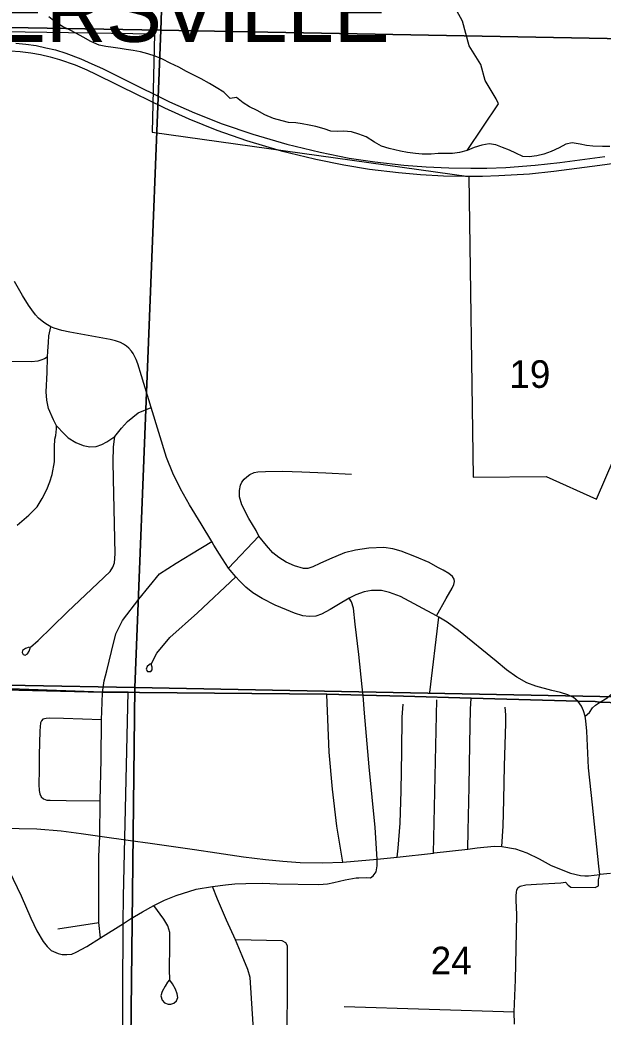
# Model space of a CAD drawing. Extents: x -19 to 40.8, y -1.8 to 26.1.
# Drawn here: x 6.121 to 7.005, y 15.443 to 16.956 of the extents above; entities that cross this region are included whole.
import ezdxf

# ---------------------------------------------------------------- set-up
doc = ezdxf.new("R2010")
doc.units = 0
for name, color, linetype in [('GM_X_City_Street', 7, 'Continuous'), ('GM_X_Corporation', 7, 'Continuous'), ('GM_X_Major_River_Text', 7, 'Continuous'), ('GM_X_Rail_Line', 7, 'Continuous'), ('GM_X_Rail_Line_Text', 7, 'Continuous'), ('GM_X_Section', 7, 'Continuous'), ('GM_X_Section_Text', 7, 'Continuous'), ('GM_X_State_Route', 7, 'Continuous'), ('GM_X_Township_Road', 7, 'Continuous'), ('RW_P_Text', 7, 'Continuous')]:
    doc.layers.add(name, color=color, linetype=linetype)

msp = doc.modelspace()

# ---------------------------------------------------------------- linework, layer by layer
at = {"layer": 'GM_X_City_Street'}
for points in [[(5.6389, 16.9451), (6.325, 16.9348), (6.3216, 16.7856), (6.8016, 16.7183), (6.8081, 16.2623), (6.9186, 16.2633), (6.995, 16.2287), (7.0882, 16.4448)], [(6.2755, 15.1522), (6.2776, 15.5857), (6.2778, 15.6259), (6.2851, 15.9362), (6.2469, 15.9361), (6.0635, 15.9423)]]:
    msp.add_lwpolyline(points, dxfattribs=at)
at = {"layer": 'GM_X_Corporation'}
for points in [[(6.0683, 15.7291), (6.093, 15.7296), (6.1466, 15.7285), (6.1833, 15.7258), (6.2138, 15.7217), (6.2422, 15.7176)], [(6.0683, 15.7291), (6.0733, 15.7128), (6.0759, 15.7091), (6.0816, 15.7026), (6.0877, 15.6959), (6.0929, 15.689), (6.1229, 15.6269), (6.1373, 15.5931), (6.1466, 15.5737), (6.1562, 15.5575), (6.1621, 15.5501), (6.1685, 15.5443), (6.1791, 15.5394), (6.1851, 15.5381), (6.1921, 15.5378), (6.1997, 15.5386), (6.2062, 15.5414), (6.2224, 15.5504), (6.2431, 15.5632), (6.2778, 15.5852), (6.2888, 15.5919)], [(6.2422, 15.7176), (6.2886, 15.711), (6.3184, 15.7069)], [(6.3184, 15.7069), (6.3857, 15.6974), (6.4194, 15.6924), (6.4601, 15.6863), (6.493, 15.6823), (6.5195, 15.6795), (6.546, 15.6778), (6.5796, 15.6773), (6.6104, 15.6781), (6.6623, 15.6827), (6.6928, 15.6858), (6.7481, 15.6919), (6.749, 15.692)], [(6.749, 15.692), (6.7999, 15.6978), (6.814, 15.6999), (6.8397, 15.7023), (6.8517, 15.7019), (6.8722, 15.6982), (6.8892, 15.6921), (6.9082, 15.6832), (6.9265, 15.6732), (6.9556, 15.6612), (6.9708, 15.6581), (6.9771, 15.6573), (6.983, 15.6572), (6.9998, 15.6594)], [(6.6349, 15.6544), (6.646, 15.6546), (6.6524, 15.6544), (6.6564, 15.6573), (6.6612, 15.6633), (6.6626, 15.6723), (6.6623, 15.6827)], [(6.2888, 15.5919), (6.3066, 15.6028), (6.3238, 15.6124), (6.34, 15.6204), (6.3577, 15.6276), (6.3882, 15.6371), (6.413, 15.6413), (6.4324, 15.6439), (6.4468, 15.6452), (6.4632, 15.6459), (6.4885, 15.6461), (6.511, 15.6452), (6.5739, 15.644), (6.5871, 15.6451), (6.597, 15.647), (6.6142, 15.6512), (6.6309, 15.6544), (6.6349, 15.6544)]]:
    msp.add_lwpolyline(points, dxfattribs=at)
at = {"layer": 'GM_X_Rail_Line'}
for points in [[(6.9998, 15.6594), (6.9986, 15.672), (6.9888, 15.7651), (6.983, 15.8213), (6.9801, 15.8766), (6.9786, 15.8925), (6.9776, 15.8996), (6.9753, 15.9076), (6.9725, 15.9147), (6.9674, 15.9218), (6.9601, 15.9277), (6.9513, 15.9321), (6.9403, 15.9355), (6.9272, 15.9385), (6.9031, 15.9449), (6.8894, 15.9502), (6.8744, 15.9586), (6.8587, 15.9699), (6.8429, 15.9828), (6.7859, 16.0296), (6.7684, 16.0421), (6.7559, 16.0497), (6.7523, 16.052), (6.6977, 16.0809), (6.6813, 16.0874), (6.6691, 16.0902), (6.6541, 16.0902), (6.6427, 16.0882), (6.6304, 16.0837), (6.6203, 16.0785), (6.6038, 16.0688), (6.5911, 16.0612), (6.578, 16.0544), (6.5696, 16.0514), (6.5596, 16.0506), (6.5499, 16.0519), (6.537, 16.0558), (6.5249, 16.0607), (6.5079, 16.0678), (6.488, 16.0779), (6.4741, 16.0869), (6.4634, 16.0954), (6.4536, 16.1047), (6.4482, 16.1107), (6.4397, 16.1209), (6.437, 16.1242), (6.4233, 16.1454), (6.4151, 16.1592), (6.4119, 16.1643), (6.3955, 16.1912), (6.378, 16.2201), (6.3642, 16.2444), (6.3526, 16.2683), (6.3431, 16.292), (6.3198, 16.3679), (6.3055, 16.4157), (6.2997, 16.434), (6.2973, 16.4406), (6.2949, 16.4459), (6.2927, 16.4498), (6.2901, 16.4534), (6.2861, 16.4577), (6.2824, 16.4608), (6.2781, 16.4638), (6.2733, 16.4662), (6.2659, 16.4689), (6.2579, 16.4708), (6.2354, 16.475), (6.1964, 16.4822), (6.1847, 16.4848), (6.1731, 16.4884), (6.1679, 16.4904), (6.1628, 16.4932), (6.1589, 16.4956), (6.1549, 16.4986), (6.1492, 16.5035), (6.1446, 16.5084), (6.1388, 16.516), (6.1341, 16.5231), (6.1251, 16.5378), (6.113, 16.559)], [(7.0162, 15.661), (6.9998, 15.6594)]]:
    msp.add_lwpolyline(points, dxfattribs=at)
at = {"layer": 'GM_X_Rail_Line_Text'}
for p, q in [((6.437, 16.1242), (6.4831, 16.1724)), ((6.7425, 15.9355), (6.7559, 16.0497)), ((6.7481, 15.6919), (6.7529, 15.9246)), ((6.6124, 15.4591), (6.8704, 15.4511))]:
    msp.add_line(p, q, dxfattribs=at)
for points in [[(6.1168, 16.1895), (6.1345, 16.2043), (6.1472, 16.2172), (6.1545, 16.2296), (6.162, 16.2436), (6.1664, 16.2553), (6.1697, 16.2662), (6.1736, 16.2856), (6.1732, 16.3081), (6.1737, 16.3198), (6.1752, 16.3254), (6.1763, 16.3353), (6.1765, 16.3402), (6.1718, 16.3492), (6.1645, 16.3662), (6.1618, 16.3791), (6.161, 16.3918), (6.1622, 16.4209), (6.163, 16.4441), (6.1634, 16.4534), (6.1642, 16.4662), (6.165, 16.4763), (6.1679, 16.4904)], [(6.1622, 16.444), (6.1581, 16.4416), (6.1525, 16.4395), (6.1479, 16.4382), (6.1385, 16.437), (6.1089, 16.4378)], [(6.1349, 16.004), (6.1292, 16.002), (6.1248, 15.9994), (6.1242, 15.996), (6.126, 15.9933), (6.1287, 15.9921), (6.1326, 15.9942), (6.1348, 15.9981), (6.1369, 16.004), (6.1487, 16.0143), (6.1691, 16.0347), (6.1931, 16.0577), (6.2203, 16.0837), (6.2577, 16.1192), (6.2618, 16.1255), (6.2643, 16.1322), (6.2655, 16.1459), (6.2627, 16.2596), (6.2623, 16.2853), (6.263, 16.3081), (6.2646, 16.3236), (6.2749, 16.3367), (6.2841, 16.3464), (6.3, 16.3595), (6.3198, 16.3679)], [(6.1765, 16.3402), (6.188, 16.3279), (6.1943, 16.322), (6.2056, 16.3147), (6.2168, 16.31), (6.2271, 16.3082), (6.2368, 16.3089), (6.2452, 16.3116), (6.2529, 16.3157), (6.2646, 16.3236)], [(6.7523, 16.052), (6.7672, 16.0782), (6.776, 16.0936), (6.7787, 16.0992), (6.7799, 16.1037), (6.7791, 16.1075), (6.7765, 16.1116), (6.7714, 16.1162), (6.7628, 16.1211), (6.7544, 16.1253), (6.7411, 16.1325), (6.7196, 16.1416), (6.699, 16.1497), (6.6864, 16.1533), (6.6724, 16.1556), (6.6499, 16.1544), (6.6296, 16.1516), (6.6128, 16.1473), (6.5904, 16.1378), (6.5754, 16.1312), (6.565, 16.1262), (6.5572, 16.1237), (6.551, 16.1236), (6.5372, 16.1274), (6.5248, 16.1334), (6.5137, 16.1403), (6.5046, 16.1475), (6.4949, 16.1584), (6.4831, 16.1724), (6.479, 16.1812), (6.4679, 16.1994), (6.4572, 16.2201), (6.4539, 16.2324), (6.4537, 16.2417), (6.4554, 16.2501), (6.4575, 16.2548), (6.4608, 16.2591), (6.465, 16.2628), (6.4696, 16.266), (6.4759, 16.2691), (6.4816, 16.2703), (6.4932, 16.2707), (6.5191, 16.2712), (6.5485, 16.2702), (6.5846, 16.2686), (6.6235, 16.2667)], [(6.246, 15.9355), (6.2488, 15.953), (6.2526, 15.9684), (6.2598, 15.9977), (6.2665, 16.0244), (6.2765, 16.0447), (6.3014, 16.0771), (6.3327, 16.1156), (6.358, 16.1319), (6.381, 16.1459), (6.4119, 16.1643)], [(6.3188, 15.9791), (6.3168, 15.9776), (6.3137, 15.9749), (6.3126, 15.971), (6.3145, 15.9672), (6.3194, 15.9672), (6.3215, 15.9701), (6.3216, 15.9739), (6.3204, 15.9767), (6.3202, 15.9797), (6.3286, 15.9951), (6.348, 16.0187), (6.39, 16.0563), (6.4482, 16.1107)], [(6.6623, 15.6827), (6.6594, 15.7309), (6.6504, 15.8227), (6.6435, 15.904), (6.6411, 15.9308), (6.6399, 15.9442), (6.6345, 15.9929), (6.6294, 16.0391), (6.6265, 16.0636), (6.6235, 16.0732), (6.6203, 16.0785)], [(6.6104, 15.6781), (6.6012, 15.7326), (6.5947, 15.789), (6.5898, 15.8451), (6.5863, 15.9324)], [(6.6928, 15.6858), (6.6944, 15.6993), (6.6972, 15.737), (6.6987, 15.7865), (6.6998, 15.8461), (6.7006, 15.8979), (6.7021, 15.9179)], [(6.7999, 15.6978), (6.8006, 15.7255), (6.8018, 15.7923), (6.8031, 15.8574), (6.8038, 15.9106), (6.8052, 15.9263), (6.8053, 15.9276)], [(6.8517, 15.7019), (6.8537, 15.7328), (6.8544, 15.7726), (6.8557, 15.8244), (6.8573, 15.8884), (6.8577, 15.9017), (6.8567, 15.9132)], [(6.8707, 15.4323), (6.8704, 15.4511), (6.8724, 15.4996), (6.873, 15.5471), (6.8741, 15.5985), (6.8733, 15.6198), (6.8734, 15.6276), (6.8736, 15.6321), (6.8743, 15.6362), (6.8761, 15.6396), (6.8795, 15.6419), (6.8877, 15.6436), (6.9038, 15.6448), (6.9409, 15.6467), (6.9482, 15.6477), (6.9519, 15.6431), (6.9563, 15.64), (6.993, 15.6399), (6.9982, 15.6421), (6.9979, 15.6513), (6.9998, 15.6594)], [(6.4757, 15.4162), (6.4734, 15.4482), (6.4699, 15.5033), (6.4667, 15.5155), (6.4577, 15.5361), (6.4476, 15.5604), (6.4343, 15.5899), (6.4204, 15.6218), (6.413, 15.6413)], [(6.3477, 15.4994), (6.3448, 15.4958), (6.3414, 15.4899), (6.3366, 15.482), (6.3348, 15.4755), (6.3365, 15.4688), (6.3402, 15.4647), (6.3457, 15.4626), (6.3499, 15.4628), (6.3545, 15.4641), (6.3583, 15.4676), (6.3604, 15.473), (6.3595, 15.4785), (6.3569, 15.4854), (6.3523, 15.4935), (6.3483, 15.4992), (6.3479, 15.5159), (6.3484, 15.551), (6.3482, 15.5712), (6.3454, 15.5815), (6.339, 15.5916), (6.3238, 15.6124)], [(6.4753, 15.3941), (6.4893, 15.3939), (6.5009, 15.3972), (6.5112, 15.4054), (6.5216, 15.4188), (6.5249, 15.424), (6.5262, 15.4322), (6.5264, 15.4768), (6.5267, 15.5513), (6.5241, 15.5559), (6.5184, 15.5586), (6.4476, 15.5604)]]:
    msp.add_lwpolyline(points, dxfattribs=at)
at = {"layer": 'GM_X_Section'}
for points in [[(6.7991, 16.7578), (6.8466, 16.8283), (6.8431, 16.8363), (6.826, 16.8637), (6.8199, 16.8879), (6.802, 16.9165), (6.7919, 16.954), (6.7661, 17.0014)], [(6.7991, 16.7578), (6.7874, 16.7548), (6.7765, 16.7533), (6.7658, 16.7533), (6.7552, 16.753), (6.7446, 16.7523), (6.7305, 16.7522), (6.7206, 16.7531), (6.7084, 16.7546), (6.6977, 16.7565), (6.6808, 16.7606), (6.6693, 16.7644), (6.6584, 16.7705), (6.646, 16.7785), (6.6349, 16.7827), (6.6237, 16.7861), (6.6115, 16.7869), (6.6021, 16.7866), (6.5922, 16.7871), (6.5822, 16.7905), (6.5695, 16.7939), (6.5596, 16.7959), (6.5489, 16.7979), (6.5393, 16.7995), (6.5282, 16.8003), (6.5183, 16.8026), (6.5056, 16.8064), (6.4921, 16.812), (6.4805, 16.8185), (6.469, 16.8239), (6.4593, 16.83), (6.4495, 16.8381), (6.4397, 16.8366), (6.4299, 16.8462), (6.4186, 16.8535), (6.4082, 16.8592), (6.3958, 16.8664), (6.3846, 16.8718), (6.3737, 16.8775), (6.3618, 16.884), (6.3486, 16.8904), (6.337, 16.8961), (6.3262, 16.9007), (6.3151, 16.9042), (6.304, 16.9073), (6.2925, 16.9092), (6.2822, 16.9111), (6.2727, 16.9124), (6.2623, 16.9139), (6.2513, 16.9155), (6.2409, 16.9174), (6.2286, 16.9231), (6.217, 16.9296), (6.2069, 16.935), (6.1961, 16.9407), (6.1853, 16.9457), (6.1748, 16.9522), (6.1647, 16.9607)], [(7.0153, 16.7638), (7.0039, 16.7639), (6.9894, 16.7645), (6.9799, 16.7654), (6.9703, 16.7674), (6.9581, 16.7693), (6.9483, 16.7671), (6.9382, 16.7618), (6.9262, 16.7561), (6.9153, 16.7523), (6.9043, 16.7497), (6.893, 16.7482), (6.8834, 16.7487), (6.8726, 16.7537), (6.863, 16.7583), (6.8526, 16.7622), (6.8422, 16.7664), (6.8323, 16.7676), (6.8213, 16.7657), (6.8096, 16.7623), (6.7991, 16.7578)]]:
    msp.add_lwpolyline(points, dxfattribs=at)
at = {"layer": 'GM_X_State_Route'}
msp.add_line((6.1784, 15.5771), (6.2407, 15.5867), dxfattribs=at)
for points in [[(4.3769, 16.7589), (4.3704, 16.384), (4.3644, 15.9666), (5.2419, 15.956), (5.3769, 15.9544), (5.3823, 15.9544), (5.3878, 15.9543), (5.57, 15.952), (6.2458, 15.936), (6.5861, 15.9329), (6.6409, 15.9314), (6.7023, 15.9297), (6.805, 15.9268), (6.9672, 15.9223), (6.993, 15.9217), (6.9993, 15.9207), (7.1288, 15.9169)], [(6.9776, 15.8996), (6.9843, 15.9053), (6.9891, 15.912), (6.9934, 15.9162), (6.9982, 15.9194), (6.9995, 15.9202), (7.0114, 15.9273), (7.0186, 15.934), (7.0277, 15.9467), (7.044, 15.9727), (7.0593, 15.9969), (7.0813, 16.0315), (7.0933, 16.0501), (7.098, 16.0543), (7.106, 16.0577), (7.1676, 16.0804), (7.1999, 16.0937), (7.2273, 16.1065), (7.2561, 16.1185), (7.2704, 16.1253), (7.2721, 16.1264)], [(7.1288, 15.9169), (6.9993, 15.9207), (6.993, 15.9217), (6.9672, 15.9223), (6.805, 15.9268), (6.7023, 15.9297), (6.6409, 15.9314), (6.5861, 15.9329), (6.2458, 15.936), (5.57, 15.952), (5.3878, 15.9543), (5.3823, 15.9544), (5.3769, 15.9544), (5.2419, 15.956), (4.3644, 15.9666), (4.3628, 15.868), (4.3494, 15.3211)], [(6.2431, 15.5632), (6.2407, 15.5867), (6.2404, 15.6866), (6.2422, 15.7176), (6.2427, 15.7711), (6.2441, 15.834), (6.2444, 15.8942), (6.2454, 15.9205), (6.246, 15.9355)], [(6.2444, 15.8942), (6.1871, 15.896), (6.1665, 15.8965), (6.1609, 15.8962), (6.1559, 15.8949), (6.1537, 15.8925), (6.152, 15.8895), (6.151, 15.8774), (6.1504, 15.8406), (6.1504, 15.8181), (6.1498, 15.7958), (6.15, 15.787), (6.151, 15.7816), (6.1534, 15.7773), (6.1568, 15.7743), (6.1618, 15.7723), (6.167, 15.772), (6.1911, 15.7716), (6.2427, 15.7711)]]:
    msp.add_lwpolyline(points, dxfattribs=at)
at = {"layer": 'GM_X_Township_Road'}
for points in [[(6.115, 16.9206), (6.1299, 16.9191), (6.1454, 16.9168), (6.1605, 16.9136), (6.1751, 16.9102), (6.1904, 16.9054), (6.2134, 16.8966), (6.2302, 16.8894), (6.2464, 16.8819), (6.2815, 16.8644), (6.3479, 16.8317), (6.3857, 16.8149), (6.4278, 16.7983), (6.4741, 16.7823), (6.5254, 16.7674), (6.5759, 16.7551), (6.6203, 16.7463), (6.659, 16.7405), (6.703, 16.7353), (6.7366, 16.7327), (6.771, 16.7312), (6.8044, 16.7309), (6.8286, 16.731), (6.8577, 16.732), (6.902, 16.7353), (6.9395, 16.7394), (7.0077, 16.7487)], [(6.1069, 16.9091), (6.1214, 16.908), (6.1375, 16.9058), (6.1523, 16.9032), (6.1669, 16.8998), (6.1808, 16.8959), (6.2049, 16.8874), (6.2222, 16.88), (6.2362, 16.8736), (6.2677, 16.858)], [(6.2677, 16.858), (6.274, 16.8549), (6.3383, 16.8233), (6.3402, 16.8224)], [(6.3402, 16.8224), (6.3772, 16.8057), (6.4193, 16.7887), (6.4642, 16.7729), (6.5171, 16.7572), (6.5675, 16.7448), (6.5695, 16.7444)], [(6.5695, 16.7444), (6.6121, 16.7357), (6.6508, 16.7295), (6.6947, 16.7242), (6.7281, 16.7214), (6.7629, 16.7195), (6.7963, 16.7188), (6.8202, 16.7189)], [(6.8202, 16.7189), (6.8223, 16.7189), (6.847, 16.7198), (6.8933, 16.7224), (6.9304, 16.7262), (6.9998, 16.7354), (7.0406, 16.7411)]]:
    msp.add_lwpolyline(points, dxfattribs=at)
at = {"layer": 'RW_P_Text'}
msp.add_lwpolyline([(5.3496, 17.5837), (5.3629, 17.962), (6.3691, 17.9545), (6.3345, 16.9403), (5.3277, 16.9579), (5.3482, 17.5425)], dxfattribs=at)
for points in [[(6.3691, 17.9545), (7.3559, 17.9489), (7.309, 16.9219), (6.3345, 16.9403)], [(6.3345, 16.9403), (6.2953, 15.9429), (5.2973, 15.9612), (5.3277, 16.9579)], [(7.309, 16.9219), (7.2877, 15.9238), (6.2953, 15.9429), (6.3345, 16.9403)], [(5.2973, 15.9612), (6.2953, 15.9429), (6.2831, 14.8757), (5.2615, 14.8764), (5.2848, 15.9609)], [(6.2953, 15.9429), (7.2877, 15.9238), (7.2668, 14.8526), (6.2831, 14.8757)]]:
    msp.add_lwpolyline(points, close=True, dxfattribs=at)

# ---------------------------------------------------------------- texts
at = {"layer": 'GM_X_Major_River_Text'}
msp.add_text('WINTERSVILLE', height=0.094697, rotation=0, dxfattribs=at).set_placement((5.7523, 16.9225))
at = {"layer": 'GM_X_Section_Text'}
for s, p in [('19', (6.8628, 16.3976)), ('24', (6.7436, 15.5079))]:
    msp.add_text(s, height=0.04186, rotation=0, dxfattribs=at).set_placement(p)

doc.saveas('drawing.dxf')
